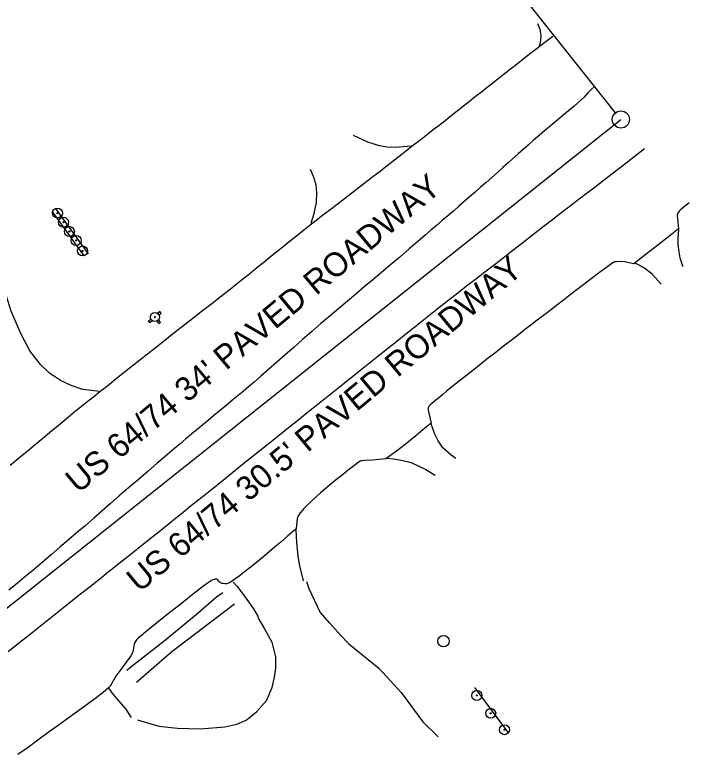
# Model space of a CAD drawing. Extents: x 471894 to 476235, y 503501 to 507878.
# Drawn here: x 473926.8 to 474229, y 506381.3 to 506701.8 of the extents above; entities that cross this region are included whole.
import ezdxf

# ---------------------------------------------------------------- set-up
doc = ezdxf.new("R2010")
doc.units = 0
for name, color, linetype in [('CTL Sheet Notes CELL', 7, 'Continuous'), ('Exist Horizontal Alignment', 7, 'Continuous'), ('Exist Other Culture Sign', 7, 'Continuous'), ('Exist Other Culture Sign Post CELL', 7, 'Continuous'), ('Exist Roads EOP', 7, 'Continuous'), ('Exist Roads EOP Other', 7, 'Continuous'), ('Exist Roads EOP Text', 7, 'Continuous'), ('Exist Structure Minor Paved Ditch or Gutter', 7, 'Continuous'), ('Exist Utilities Other Pole CELL', 7, 'Continuous'), ('Exist Utilities Water Fire Hydrant CELL', 7, 'Continuous')]:
    doc.layers.add(name, color=color, linetype=linetype)

msp = doc.modelspace()

# ---------------------------------------------------------------- linework, layer by layer
at = {"layer": 'Exist Horizontal Alignment'}
for p, q in [((474188.62, 506659.12), (474113.58, 506753.46)), ((473294.53, 505943.19), (474190.95, 506656.19))]:
    msp.add_line(p, q, dxfattribs=at)
msp.add_circle((474190.95, 506656.19), 3.75, dxfattribs=at)
at = {"layer": 'Exist Other Culture Sign'}
for p, q in [((473944.44, 506617.58), (473958.76, 506597.66)), ((473957.05, 506596.77), (473943.1, 506616.24)), ((474127.18, 506408.74), (474141.92, 506388.78))]:
    msp.add_line(p, q, dxfattribs=at)
at = {"layer": 'Exist Other Culture Sign Post CELL'}
for centre, radius in [((473945.39, 506615.42), 2.18), ((473945.39, 506615.42), 0.24), ((473947.99, 506611.42), 2.18), ((473947.99, 506611.42), 0.24), ((473950.58, 506607.37), 2.18), ((473950.58, 506607.37), 0.24), ((473953.54, 506603.49), 2.18), ((473953.54, 506603.49), 0.24), ((473956.36, 506598.89), 2.18), ((473956.36, 506598.89), 0.24), ((474128.17, 506405.23), 2.18), ((474128.17, 506405.23), 0.24), ((474134.21, 506397.43), 2.18), ((474134.21, 506397.43), 0.24), ((474140.19, 506390.29), 2.18), ((474140.19, 506390.29), 0.24)]:
    msp.add_circle(centre, radius, dxfattribs=at)
at = {"layer": 'Exist Roads EOP'}
for points in [[(473924.81, 506505.61), (473927.47, 506507.78), (473930.06, 506509.9), (473932.57, 506511.96), (473935.01, 506513.98), (473937.4, 506515.96), (473939.77, 506517.92), (473942.1, 506519.87), (473946.59, 506523.64), (473950.26, 506526.69), (473953.12, 506529.03), (473955.83, 506531.21), (473958.81, 506533.58), (473961.04, 506535.35), (473963.87, 506537.61), (473967.29, 506540.33), (473970.96, 506543.26), (473974.52, 506546.09), (473977.99, 506548.83), (473981.36, 506551.49), (473984.68, 506554.1), (473988.01, 506556.73), (473991.35, 506559.37), (473994.7, 506562.02), (473998.02, 506564.64), (474001.25, 506567.18), (474004.4, 506569.64), (474007.48, 506572.03), (474010.42, 506574.31), (474013.19, 506576.46), (474015.78, 506578.49), (474018.19, 506580.38), (474020.62, 506582.31), (474023.27, 506584.41), (474026.13, 506586.69), (474029.21, 506589.14), (474032.33, 506591.65), (474035.35, 506594.08), (474038.26, 506596.43), (474041.07, 506598.7), (474043.76, 506600.88), (474046.35, 506602.97), (474048.83, 506604.96), (474053.45, 506608.65), (474057.44, 506611.77), (474060.92, 506614.44), (474064.8, 506617.4), (474069.16, 506620.74), (474073.71, 506624.24), (474078.41, 506627.88), (474080.86, 506629.78), (474083.39, 506631.73), (474085.98, 506633.74), (474088.56, 506635.73), (474091.02, 506637.64), (474095.6, 506641.21), (474099.98, 506644.64), (474104.45, 506648.12), (474109.17, 506651.81), (474111.69, 506653.77), (474114.31, 506655.82), (474116.98, 506657.92), (474119.65, 506660.01), (474122.31, 506662.11), (474124.96, 506664.21), (474127.59, 506666.29), (474130.15, 506668.31), (474132.66, 506670.28), (474135.11, 506672.2), (474137.51, 506674.07), (474142.17, 506677.73), (474146.59, 506681.2), (474150.46, 506684.23), (474153.82, 506686.83), (474157.17, 506689.39), (474161.23, 506692.45)], [(474179.35, 506670.35), (474178.02, 506669.25), (474176.6, 506667.82), (474175, 506665.94), (474170.55, 506662), (474167.31, 506659.29), (474162.76, 506655.49), (474160.2, 506653.35), (474157.7, 506651.23), (474155.28, 506649.16), (474152.92, 506647.12), (474150.62, 506645.11), (474146.15, 506641.16), (474141.79, 506637.26), (474139.51, 506635.23), (474137.15, 506633.14), (474134.69, 506630.97), (474132.21, 506628.79), (474129.77, 506626.65), (474127.38, 506624.54), (474125.03, 506622.48), (474122.69, 506620.42), (474120.33, 506618.36), (474117.93, 506616.28), (474115.51, 506614.2), (474113.07, 506612.11), (474110.63, 506610.01), (474108.17, 506607.89), (474105.7, 506605.77), (474103.27, 506603.68), (474098.73, 506599.79), (474094.55, 506596.24), (474090.52, 506592.84), (474086.6, 506589.55), (474082.8, 506586.34), (474079.1, 506583.21), (474075.44, 506580.11), (474071.77, 506577.02), (474068.03, 506573.86), (474064.18, 506570.62), (474060.23, 506567.24), (474056.19, 506563.75), (474052.22, 506560.29), (474048.37, 506556.9), (474044.61, 506553.6), (474040.96, 506550.39), (474037.42, 506547.27), (474034.04, 506544.29), (474031.15, 506541.76), (474028.72, 506539.68), (474026.28, 506537.62), (474022, 506534.1), (474018.04, 506530.86), (474013.5, 506527.13), (474011.16, 506525.18), (474008.76, 506523.19), (474006.33, 506521.15), (474003.87, 506519.09), (474001.39, 506517), (473998.89, 506514.89), (473996.48, 506512.85), (473992.28, 506509.28), (473988.75, 506506.24), (473984.87, 506502.91), (473980.55, 506499.21), (473976.35, 506495.62), (473972.35, 506492.19), (473968.54, 506488.87), (473964.89, 506485.65), (473961.19, 506482.41), (473957.42, 506479.17), (473953.73, 506476.01), (473950.13, 506472.93), (473946.45, 506469.79), (473942.67, 506466.55), (473938.69, 506463.17), (473934.6, 506459.72), (473931.03, 506456.71), (473927.92, 506454.1), (473924.26, 506451.05)], [(473923.9, 506424.31), (473928.45, 506427.93), (473932.89, 506431.48), (473937.27, 506434.97), (473941.65, 506438.45), (473946.03, 506441.93), (473950.4, 506445.43), (473954.89, 506449.01), (473959.59, 506452.73), (473962, 506454.63), (473964.4, 506456.53), (473966.8, 506458.43), (473969.2, 506460.34), (473971.58, 506462.23), (473976.17, 506465.89), (473980.6, 506469.43), (473985.1, 506473.01), (473989.71, 506476.67), (473992.06, 506478.55), (473994.44, 506480.46), (473996.85, 506482.41), (473999.25, 506484.35), (474003.89, 506488.09), (474008.32, 506491.65), (474012.62, 506495.09), (474016.83, 506498.45), (474021.03, 506501.81), (474025.23, 506505.2), (474029.44, 506508.56), (474033.64, 506511.91), (474037.85, 506515.29), (474042.11, 506518.75), (474046.78, 506522.5), (474049.28, 506524.51), (474051.8, 506526.52), (474054.23, 506528.47), (474058.85, 506532.15), (474063.25, 506535.66), (474067.54, 506539.07), (474071.84, 506542.48), (474076.25, 506546.01), (474080.67, 506549.55), (474084.98, 506553), (474089.18, 506556.34), (474093.28, 506559.58), (474097.27, 506562.74), (474101.16, 506565.86), (474104.93, 506568.89), (474108.6, 506571.8), (474112.26, 506574.69), (474116.04, 506577.64), (474119.88, 506580.64), (474123.72, 506583.64), (474127.63, 506586.68), (474131.65, 506589.77), (474135.67, 506592.87), (474139.59, 506595.92), (474143.34, 506598.85), (474146.86, 506601.57), (474150.28, 506604.21), (474153.7, 506606.88), (474157.13, 506609.54), (474160.56, 506612.2), (474164.05, 506614.9), (474167.66, 506617.7), (474171.39, 506620.57), (474175.24, 506623.5), (474179.15, 506626.46), (474183.07, 506629.44), (474187.05, 506632.5), (474191.15, 506635.69), (474195.25, 506638.9), (474199.22, 506642), (474201.22, 506643.55)], [(474220.67, 506619.93), (474217.26, 506617.16), (474216.3, 506616.19), (474216.04, 506615.82), (474215.76, 506615.32), (474215.63, 506615.03), (474215.55, 506614.7), (474215.51, 506614.32), (474216.04, 506608.52), (474211.69, 506605.07), (474206.99, 506601.4), (474201.96, 506597.49), (474196.59, 506593.36), (474192.53, 506594.15), (474190.57, 506594.27), (474188.99, 506594.21), (474188.69, 506594.17), (474188.38, 506594.1), (474188.07, 506594), (474187.76, 506593.87), (474187.06, 506593.49), (474184.64, 506591.72), (474181.69, 506589.5), (474177.43, 506586.27), (474174.83, 506584.28), (474171.91, 506582.04), (474168.87, 506579.71), (474165.89, 506577.41), (474162.96, 506575.17), (474160.1, 506572.97), (474157.28, 506570.81), (474154.49, 506568.68), (474151.73, 506566.56), (474149.01, 506564.47), (474146.32, 506562.4), (474143.65, 506560.34), (474141.01, 506558.3), (474138.4, 506556.26), (474135.83, 506554.25), (474133.31, 506552.29), (474130.85, 506550.36), (474128.45, 506548.47), (474123.77, 506544.76), (474119.2, 506541.11), (474115.02, 506537.74), (474113.18, 506536.25), (474110.09, 506533.73), (474107.87, 506531.84), (474107.66, 506531.6), (474107.46, 506531.34), (474107.28, 506531.06), (474107.13, 506530.77), (474107.01, 506530.46), (474106.93, 506530.14), (474106.91, 506529.81), (474106.93, 506529.47), (474108.3, 506523.89), (474104.69, 506520.89), (474101.6, 506518.34), (474097, 506514.62), (474093.11, 506511.66), (474088.56, 506508.35), (474082.71, 506507.69), (474079.2, 506507.61), (474078.2, 506507.5), (474077.99, 506507.46), (474077.79, 506507.41), (474077.37, 506507.24), (474076.89, 506506.98), (474072.13, 506503.36), (474069.41, 506501.22), (474066.48, 506498.89), (474063.86, 506496.75), (474060.05, 506493.48), (474056.63, 506490.38), (474052.82, 506486.73), (474050.86, 506484.38), (474050.41, 506483.67), (474050.05, 506482.91), (474049.89, 506482.29), (474049.45, 506477.81), (474045.87, 506474.72), (474042.69, 506471.99), (474039.89, 506469.62), (474035.32, 506465.81), (474031.23, 506462.47), (474027.53, 506459.51), (474024.66, 506457.26), (474020.73, 506454.46), (474020.31, 506454.24), (474019.9, 506454.08), (474019.5, 506453.96), (474019.1, 506453.9), (474018.33, 506453.87), (474017.55, 506453.94), (474017.17, 506454.01), (474016.83, 506454.13), (474016.52, 506454.29), (474016.24, 506454.48), (474015.76, 506454.91), (474015.56, 506455.13), (474015.23, 506455.55), (474014.97, 506455.81), (474014.77, 506455.9), (474014.47, 506455.91), (474014.08, 506455.86), (474013.68, 506455.78), (474013.27, 506455.66), (474012.87, 506455.51), (474012.46, 506455.32), (474012.05, 506455.06), (474009.84, 506453.38), (474005.47, 506450), (474001.81, 506447.15), (473997.98, 506444.15), (473994.36, 506441.3), (473990.95, 506438.6), (473986.31, 506434.86), (473983.89, 506432.91), (473980.51, 506430.13), (473980.05, 506429.62), (473979.58, 506429.02), (473979.18, 506428.34), (473978.86, 506427.58), (473978.64, 506426.75), (473978.27, 506424.26), (473978.14, 506423.86), (473977.96, 506423.45), (473977.43, 506422.54), (473975.4, 506419.77), (473973, 506416.57), (473970.9, 506413.58), (473968.31, 506409.28), (473967.67, 506408.54), (473965.38, 506406.5), (473961.07, 506403.26), (473957.3, 506400.49), (473953.15, 506397.48), (473949.44, 506394.84), (473945.68, 506392.15), (473941.36, 506389.01), (473936.87, 506385.71), (473932.58, 506382.58), (473928.18, 506379.42)]]:
    msp.add_lwpolyline(points, dxfattribs=at)
at = {"layer": 'Exist Roads EOP Other'}
for points in [[(474155.46, 506688.26), (474156.05, 506690.42), (474156.28, 506692.76), (474155.77, 506695.45), (474154.82, 506697.93)], [(474099.56, 506644.51), (474094.34, 506644.15), (474089.81, 506643.92), (474085.72, 506644.73), (474080.63, 506646.33), (474074.4, 506649.25)], [(474055.92, 506610.94), (474057.3, 506615.26), (474058.3, 506620.03), (474058.46, 506624.26), (474058.1, 506627.65), (474056.98, 506631.34), (474055.75, 506634.35)], [(473963.76, 506537.69), (473956.52, 506538.6), (473951.34, 506540.32), (473946.68, 506542.39), (473941.87, 506545.69), (473938.03, 506549.48), (473933.29, 506555.41), (473929.34, 506563.28), (473925.29, 506572.69), (473921.59, 506584.27), (473918.36, 506598.97), (473914.85, 506609.83), (473910.7, 506617.87), (473904.19, 506627.56), (473902.72, 506630.24)], [(474215.99, 506608.23), (474215.82, 506604.41), (474215.84, 506601.74), (474216.18, 506598.52), (474216.62, 506595.92), (474217.75, 506592.48), (474217.92, 506592.08)], [(474208.47, 506584.37), (474207.39, 506585.68), (474204.53, 506588.73), (474201.22, 506591.35), (474198.57, 506592.83), (474197.02, 506593.52)], [(474118.97, 506508.44), (474116.99, 506509.97), (474113.34, 506513.09), (474111.3, 506516.18), (474109.68, 506519.33), (474108.24, 506523.56)], [(474089, 506508.54), (474091.8, 506508.35), (474095.31, 506507.78), (474099.55, 506506.77), (474105.98, 506503.67), (474109.94, 506501.23)], [(474049.36, 506477.34), (474049.52, 506471.91), (474050.14, 506465.96), (474050.9, 506461.67), (474052.38, 506455.78), (474052.56, 506455.21)], [(474021.91, 506454.61), (474023.7, 506452.75), (474026.53, 506449.07), (474030.82, 506442.92), (474032.9, 506439.51)], [(474059.85, 506441.51), (474055.12, 506451.64), (474054.15, 506454.73)], [(474072.37, 506427.67), (474068.97, 506431.29), (474064.09, 506436.74), (474059.85, 506441.51)], [(474032.66, 506439.12), (474035.63, 506434.24), (474038.85, 506428.49)], [(474038.85, 506428.49), (474040.48, 506422.06), (474040.42, 506417.29), (474039.81, 506413.12), (474038.71, 506408.12)], [(474072.37, 506427.67), (474085.42, 506417.16), (474095.24, 506406.48), (474100.55, 506399.28), (474104.63, 506393.75), (474110.84, 506387.6), (474111.25, 506387.24)], [(473967.76, 506408.22), (473969.17, 506406.41), (473971.35, 506403.8), (473974.99, 506399.36), (473977.58, 506395.53)], [(474007.8, 506390.72), (474018.4, 506391.52), (474023.57, 506392.74), (474027.61, 506394.41), (474032.28, 506398.2), (474036.6, 506403.18), (474038.71, 506408.12)], [(473980.29, 506394.61), (473989.51, 506391.86), (473997.65, 506390.9), (474007.8, 506390.72)]]:
    msp.add_lwpolyline(points, dxfattribs=at)
at = {"layer": 'Exist Structure Minor Paved Ditch or Gutter'}
for points in [[(473975.69, 506416.18), (473976.69, 506417.14), (473991.86, 506429.03), (474005.81, 506440.52), (474014.75, 506448.24), (474017.42, 506450.05)], [(474022.55, 506444.99), (473995.29, 506424.16), (473979.8, 506410.91)]]:
    msp.add_lwpolyline(points, dxfattribs=at)
at = {"layer": 'Exist Utilities Other Pole CELL'}
msp.add_circle((474113.64, 506428.86), 2.46, dxfattribs=at)
at = {"layer": 'Exist Utilities Water Fire Hydrant CELL'}
msp.add_line((473987.85, 506570.07), (473987.85, 506570.07), dxfattribs=at)
for points in [[(473989.65, 506570.9), (473990.63, 506571.73), (473989.98, 506572.51), (473988.97, 506571.67)], [(473986.71, 506568.45), (473985.73, 506567.62), (473985.07, 506568.41), (473986.08, 506569.25)], [(473988.69, 506568.27), (473989.51, 506567.29), (473990.3, 506567.94), (473989.47, 506568.93)]]:
    msp.add_lwpolyline(points, dxfattribs=at)
for radius in [1.98, 0.243]:
    msp.add_circle((473987.85, 506570.07), radius, dxfattribs=at)

# ---------------------------------------------------------------- texts
at = {"layer": 'CTL Sheet Notes CELL'}
msp.add_text('1.  PROJECT CONTROL WAS ESTABLISHED USING GNSS,  THE GLOBAL NAVIGATION SATELLITE SYSTEM.', height=16.6056, rotation=133.7933, dxfattribs=at).set_placement((474389.04, 506685.47))
at = {"layer": 'Exist Roads EOP Text'}
for s, p in [("US 64/74 34' PAVED ROADWAY", (473954.43, 506492.96)), ("US 64/74 30.5' PAVED ROADWAY", (473981.04, 506449.78))]:
    msp.add_text(s, height=10.4, rotation=39.7704, dxfattribs=at).set_placement(p)

doc.saveas('drawing.dxf')
